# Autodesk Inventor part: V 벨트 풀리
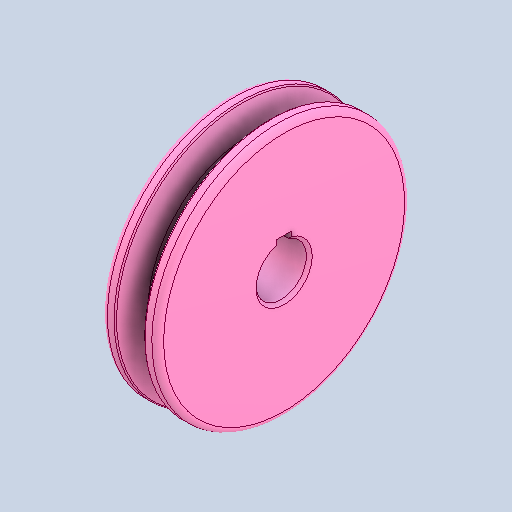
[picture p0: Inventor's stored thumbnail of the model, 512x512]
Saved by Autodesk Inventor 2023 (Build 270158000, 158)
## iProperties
Created: 2025-03
Part Number: V 벨트 풀리
Material: 알루미늄 6061
Document SubType Name: Modeling
Designer: user
Density: 2.71 g/cm^3
Appearance: 기본값
Author: jhkim
Sending System: Autodesk Inventor 2025
Preprocessor: ST-DEVELOPER v20
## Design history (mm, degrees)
feature "솔리드1"
node "솔리드2"
